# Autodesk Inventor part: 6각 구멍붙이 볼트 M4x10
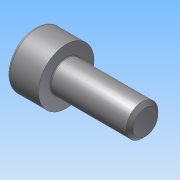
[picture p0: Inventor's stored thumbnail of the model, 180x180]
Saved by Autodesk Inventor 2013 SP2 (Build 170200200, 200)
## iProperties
Created: 2025-09
Part Number: 6각 구멍붙이 볼트 M4x10
Material: Generic
Document SubType Name: Modeling
Designer: a
Density: 1 g/cm^3
Author: a
변환 표준: STEP AP214IS
전처리기: Build: 200, Release: 2013 SP2 Update 6 - Date: Thu 07/17/2014
전송 단위: 밀리미터
불확실성: 0.01
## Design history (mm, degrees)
node "6각 구멍붙이 볼트 M4x101"
body "Solid1"
node "기준1"
